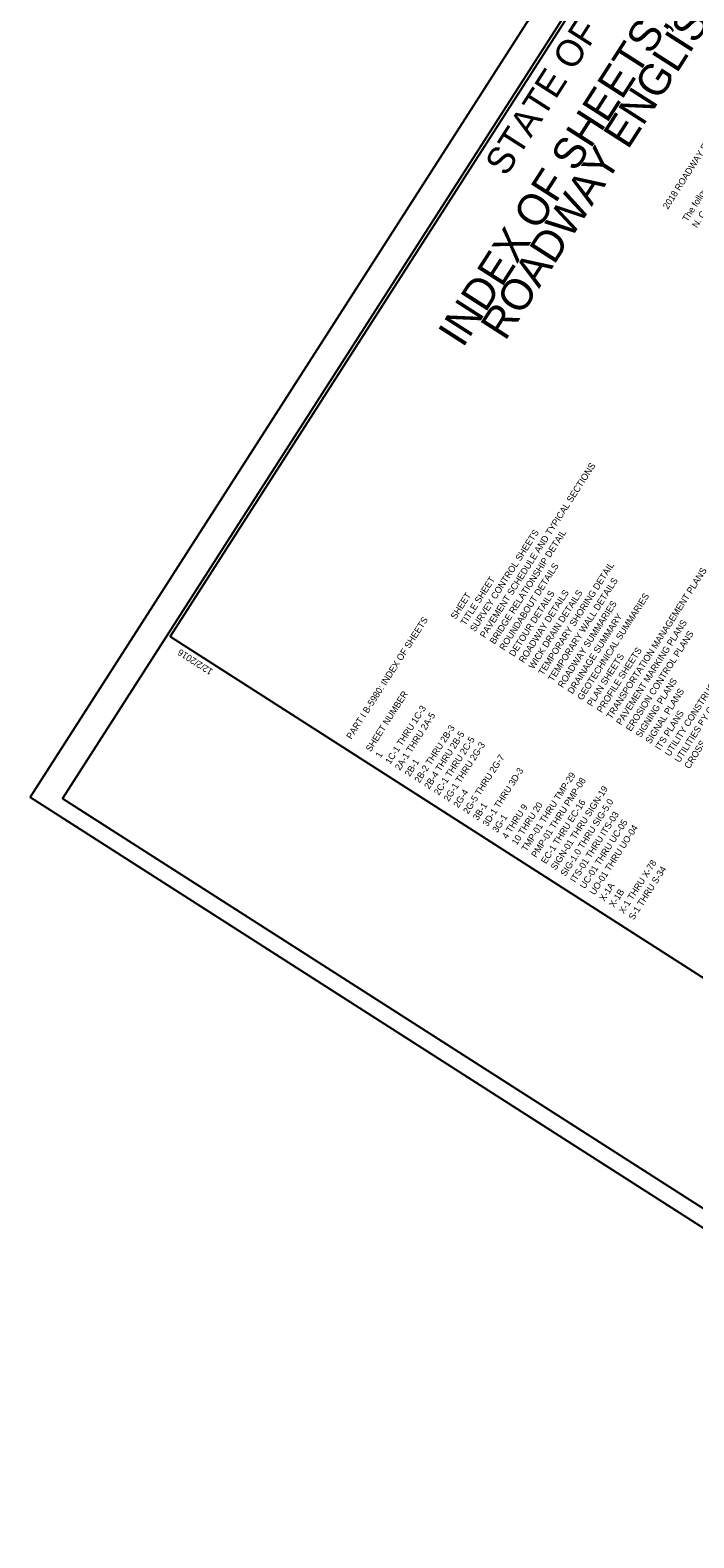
# Model space of a CAD drawing. Extents: x 2347249 to 2361994, y 830101 to 846299.
# Drawn here: x 2347249 to 2351497, y 830101 to 839761 of the extents above; entities that cross this region are included whole.
import ezdxf

# ---------------------------------------------------------------- set-up
doc = ezdxf.new("R2010")
doc.units = 0
for name, color, linetype in [('Sheet Data Field CELL', 7, 'Continuous'), ('Sheet Plot Border Inside CELL', 7, 'Continuous'), ('Sheet Plot Border Outside CELL', 7, 'Continuous'), ('Sheet Summary Guardrail CELL', 7, 'Continuous'), ('Sheet Symbology CELL', 7, 'Continuous')]:
    doc.layers.add(name, color=color, linetype=linetype)

msp = doc.modelspace()

# ---------------------------------------------------------------- linework, layer by layer
at = {"layer": 'Sheet Plot Border Inside CELL'}
msp.add_lwpolyline([(2354564.1, 830285.9), (2361823.6, 841618.9), (2354715.9, 846171.7), (2347456.5, 834838.7)], close=True, dxfattribs=at)
at = {"layer": 'Sheet Plot Border Outside CELL'}
msp.add_lwpolyline([(2354658.7, 830100.6), (2361994.4, 841552.6), (2354584.3, 846299.2), (2347248.6, 834847.2)], close=True, dxfattribs=at)
at = {"layer": 'Sheet Symbology CELL'}
msp.add_lwpolyline([(2354678.6, 846075.7), (2348144.5, 835875), (2355211, 831348.5), (2361745.1, 841549.2)], close=True, dxfattribs=at)

# ---------------------------------------------------------------- texts
at = {"layer": 'Sheet Data Field CELL'}
for s, height, p in [('INDEX OF SHEETS, GENERAL NOTES AND 2018 ', 200, (2350018.7, 837720)), ('ROADWAY ENGLISH STANDARD DRAWINGS', 200, (2350290, 837764.1)), ('The following Roadway Standards as appear in "Roadway Standard Drawings" Highway Design Branch -', 42, (2351455.7, 838530.2)), ('N. C. Department of Transportation - Raleigh, N. C., Dated January, 2018 are applicable to this ', 42, (2351518, 838490.3)), ('2018 ROADWAY ENGLISH STANDARD DRAWINGS', 42, (2351331.1, 838610)), ('PAVEMENT SCHEDULE AND TYPICAL SECTIONS', 42, (2350159.7, 835862.8)), ('SURVEY CONTROL SHEETS', 42, (2350097.3, 835902.7)), ('BRIDGE RELATIONSHIP DETAIL', 42, (2350222, 835822.8)), ('ROUNDABOUT DETAILS', 42, (2350284.3, 835782.9)), ('TEMPORARY SHORING DETAIL', 42, (2350533.6, 835623.2)), ('TRANSPORTATION MANAGEMENT PLANS', 42, (2350969.8, 835343.8)), ('TITLE SHEET', 42, (2350035, 835942.6)), ('TEMPORARY WALL DETAILS', 42, (2350595.9, 835583.3)), ('SHEET', 42, (2349972.7, 835982.5)), ('DETOUR DETAILS', 42, (2350346.6, 835743)), ('ROADWAY DETAILS', 42, (2350408.9, 835703.1)), ('WICK DRAIN DETAILS', 42, (2350471.3, 835663.2)), ('ROADWAY SUMMARIES', 42, (2350658.2, 835543.4)), ('GEOTECHNICAL SUMMARIES', 42, (2350782.9, 835463.6)), ('PART I B-5980: INDEX OF SHEETS', 42, (2349304.4, 835213.6)), ('DRAINAGE SUMMARY', 42, (2350720.5, 835503.5)), ('PAVEMENT MARKING PLANS', 42, (2351032.1, 835303.9)), ('EROSION CONTROL PLANS', 42, (2351094.5, 835264)), ('PROFILE SHEETS', 42, (2350907.5, 835383.7)), ('UTILITY CONSTRUCTION PLANS', 42, (2351343.7, 835104.3)), ('PLAN SHEETS', 42, (2350845.2, 835423.6)), ('UTILITIES BY OTHERS PLANS', 42, (2351406.1, 835064.4)), ('SIGNING PLANS', 42, (2351156.8, 835224)), ('SHEET NUMBER', 42, (2349429, 835133.7)), ('SIGNAL PLANS', 42, (2351219.1, 835184.1)), ('CROSS SECTION INDEX', 42, (2351468.4, 835024.4)), ('1C-1 THRU 1C-3', 42, (2349553.6, 835053.9)), ('2A-1 THRU 2A-5', 42, (2349616, 835014)), ('ITS PLANS', 42, (2351281.4, 835144.2)), ('2B-2 THRU 2B-3', 42, (2349740.6, 834934.1)), ('2B-4 THRU 2B-5', 42, (2349802.9, 834894.2)), ('2C-1 THRU 2C-5', 42, (2349865.2, 834854.3)), ('1', 42, (2349491.3, 835093.8)), ('2G-1 THRU 2G-3', 42, (2349927.6, 834814.4)), ('2G-5 THRU 2G-7', 42, (2350052.2, 834734.5)), ('2B-1', 42, (2349678.3, 834974)), ('3D-1 THRU 3D-3', 42, (2350176.8, 834654.7)), ('TMP-01 THRU TMP-29', 42, (2350426.1, 834495)), ('PMP-01 THRU PMP-08', 42, (2350488.4, 834455.1)), ('2G-4', 42, (2349989.9, 834774.4)), ('EC-1 THRU EC-16', 42, (2350550.8, 834415.2)), ('SIGN-01 THRU SIGN-19', 42, (2350613.1, 834375.2)), ('SIG-1.0 THRU SIG-5.0', 42, (2350675.4, 834335.3)), ('3B-1', 42, (2350114.5, 834694.6)), ('4 THRU 9', 42, (2350301.5, 834574.8)), ('10 THRU 20', 42, (2350363.8, 834534.9)), ('ITS-01 THRU ITS-03', 42, (2350737.7, 834295.4)), ('3G-1', 42, (2350239.2, 834614.8)), ('UC-01 THRU UC-05', 42, (2350800, 834255.5)), ('UO-01 THRU UO-04', 42, (2350862.4, 834215.6)), ('X-1 THRU X-78', 42, (2351049.3, 834095.8)), ('S-1 THRU S-34', 42, (2351111.6, 834055.9)), ('X-1A', 42, (2350924.7, 834175.6)), ('X-1B', 42, (2350987, 834135.7))]:
    msp.add_text(s, height=height, rotation=57.35811, dxfattribs=at).set_placement(p)
at = {"layer": 'Sheet Summary Guardrail CELL'}
msp.add_text('12/2/2016', height=42.4, rotation=147.35811, dxfattribs=at).set_placement((2348422.8, 835661.8))
at = {"layer": 'Sheet Symbology CELL'}
msp.add_text('STATE OF NORTH CAROLINA, DIVISION OF HIGHWAYS', height=171.352, rotation=57.35811, dxfattribs=at).set_placement((2350295.6, 838818.4))

doc.saveas('drawing.dxf')
